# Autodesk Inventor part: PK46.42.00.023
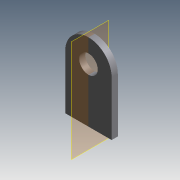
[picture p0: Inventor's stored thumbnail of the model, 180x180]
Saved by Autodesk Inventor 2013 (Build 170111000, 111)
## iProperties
Shininess: 25.0
Length Units: 11269
Angle Units: 11279
Time Units: 11290
Mass Units: 11283
Length Display Precision: 3
Angle Display Precision: 2
Created: 2001-08
Part Number: PK46.42.00.023
Material: Steel, Mild
Document SubType Name: Modeling
Designer: SOleg
Density: 7.86 g/cm^3
Mass: 40.568 g
Surface Area: 33.1996 cm^2
Volume: 5.16133 cm^3
Density: 0.0
Volumn: 0.0
Area: 0.0
PropertySet Name: Model Information
Control State: 0
Master: False
Checked Out: True
Checked Out Date: 2008-10-15
Last Check In Date: 2008-10-15
Author: SOleg
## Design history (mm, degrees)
node "ExtrusionBlind1" dims "d4" = 4, "d5" = 0
  sketch "Sketch1"
    geometry: L1 (258, 284)-(258, 249); L2 (258, 249)-(228, 249); L3 (228, 284)-(228, 249); A1 r 15 centre (243, 284) between (258, 284) and (228, 284)
    constraints: 6 end point, 2 point on circle, 2 tangent, 2 vertical, 1 centre point, 1 horizontal, 1 other
    dimensions: "d1" = 15 radius of A1; "d3" = 35 vertical distance of L1.end A1.centre
node "Hole1" dims "d7" = 12, "d8" = 4, "d9" = 2, "d10" = 60 deg, "d11" = 8, "d12" = 118 deg
  sketch "Sketch2"
    geometry: A1 r 15 centre (243, 284) between (258, 284) and (228, 284) reference; 1 further point
workplane "Work Plane2"
body "Solid1"
other parameters: "d0" = 15 (derived), "d2" = 35 (derived), "d6" = 0
